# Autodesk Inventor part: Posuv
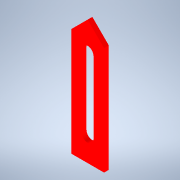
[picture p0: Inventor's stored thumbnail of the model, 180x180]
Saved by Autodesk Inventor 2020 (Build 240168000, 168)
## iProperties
Created: 2021-01
Part Number: Posuv
Material: Všeobecné
Document SubType Name: Modeling
Designer: Pavel
Density: 1 g/cm^3
Appearance: Výchozí
Author: Pavel
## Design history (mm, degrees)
sketch "Náčrt1"
  geometry: L1 (0, 0)-(14, 0); L2 (14, 0)-(14, 46); L3 (0, 46)-(0, 0); L4 (7, 40.833)-(7, 10); L5 (4.5, 40.833)-(4.5, 10); L6 (9.5, 10)-(9.5, 40.833); L7 (7, 53)-(0, 46); L8 (7, 53)-(14, 46); A1 r 2.5 centre (7, 40.833) between (9.5, 40.833) and (4.5, 40.833); A2 r 2.5 centre (7, 10) between (4.5, 10) and (9.5, 10); 1 further point
  constraints: 18 end point, 4 point on circle, 4 tangent, 2 centre point, 2 parallel, 1 horizontal, 1 midpoint, 1 perpendicular, 1 vertical
  dimensions: "d1" = 5 diameter of A2; "d2" = 45 deg angle of L7 L3; "d3" = 45 deg angle of L2 L8
extrude "Vysunutí1" new body sketch "Náčrt1" distance "d4" = 2; taper "d5" = 0 deg
node "Těleso1"
